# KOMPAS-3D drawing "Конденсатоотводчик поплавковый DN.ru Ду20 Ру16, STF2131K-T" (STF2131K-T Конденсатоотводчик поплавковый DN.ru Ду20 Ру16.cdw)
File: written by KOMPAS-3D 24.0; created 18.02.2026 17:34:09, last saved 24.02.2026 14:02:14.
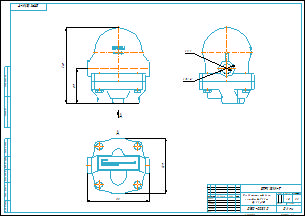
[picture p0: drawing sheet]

Document properties: арт: D150-00320; Автор: R2D2; Форматы листов документа: A2; Полное имя файла: ..\DN15\STF2131K-T Конденсатоотводчик поплавковый DN.ru Ду15 Ру16.cdw; Масса: 2.8; Наименование: Конденсатоотводчик поплавковый DN.ru Ду20 Ру16; Количество листов документа: 1; Примечание: D150-00320

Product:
- Part/product: Конденсатоотводчик поплавковый DN.ru Ду20 Ру16  | designation STF2131K-T
    Масса: 2.8
    Раздел спецификации: Прочие изделия
    Форматы листов документа: A2
    Примечание: D150-00320
    additional columns: D150-00320

Views: Вид по стрелке А
Referenced files in E:\Работа\Зайцев\Для компаса\: чертеж DN.ru А3.cdt
Referenced files in E:\Работа\Зайцев\STF2131K-T Конденсатоотводчик поплавковый DN.ru Ду15-50 Ру16\DN20\: STF2131K-T Конденсатоотводчик поплавковый DN.ru Ду20 Ру16.m3d
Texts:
  чертеж DN.ru А3.cdt
  Конденсатоотводчик
  поплавковый DN.ru
  Ду20 Ру16
  STF2131K-T
  Конденсатоотводчик поплавковый DN.ru Ду20 Ру16
  STF2131K-T Конденсатоотводчик поплавковый DN.ru Ду20 Ру16
Dimensions and other numbers on the sheet: 1:1; 0; 1; 2; 2,8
